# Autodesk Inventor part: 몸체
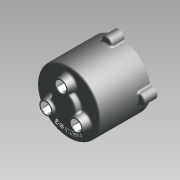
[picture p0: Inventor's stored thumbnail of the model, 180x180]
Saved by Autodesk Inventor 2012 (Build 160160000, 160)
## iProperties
Created: 2012-05
Part Number: 몸체
Document SubType Name: 모델링
Designer: SeoGD™
Material: 알루미늄-6061
Mass: 475.555 g
Surface Area: 687.662 cm^2
Volume: 175.481 cm^3
Density: 2.71 g/cm^3
변환 표준: STEP AP214IS
파일 이름: C:\Users\SeoGD\Desktop\?쒗뿕\紐몄껜.stp
전처리기: Build: 253, Release: 2010 SP1 - Date: Wed 07/29/2009
전송 단위: 밀리미터
불확실성: 0.01
Author: SeoGD™
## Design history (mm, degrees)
sketch "스케치2"
  geometry: C1 r 50 at (0, 0); 1 further point
  constraints: 1 centre point, 1 coincident
  dimensions: "d9" = 100 diameter of C1
extrude "돌출2" new body sketch "스케치2" distance "d10" = 80; taper "d11" = 0 deg
feature "쉘1" dims "d12" = 5
sketch "스케치3" dims "d13" = 55
  geometry: C1 r 7.5 at (0, 27.5); C2 r 12.5 at (0, 27.5); 2 further points
  constraints: 2 centre point, 2 coincident, 2 vertical alignment, 2 other
  dimensions: "d14" = 15 diameter of C1; "d15" = 25 diameter of C2
extrude "돌출3" join sketch "스케치3" distance "d16" = 12; taper "d17" = -10 deg
hole "구멍2" diameter "d20" = 15; stored, may be unused: countersink angle "d24" = 90 deg, drill point angle "d26" = 118 deg; dims "d18" = 10, "d19" = 10, "d21" = 6, "d22" = 4, "d23" = 2, "d25" = 15
chamfer "모따기1" distance "d27" = 1; stored, may be unused: second distance "d28" = 2, angle "d29" = 45 deg
sketch "스케치4"
  geometry: L1 (0, 0)-(0, 88); L2 (0, 70)-(13.16, 70); L3 (-45, 75)-(45, 75) reference; L4 (-50, 80)-(50, 80) reference; L5 (13.16, 70)-(14.5, 75); L6 (20, 80)-(20, 88); L7 (20, 88)-(0, 88); L8 (20, 80)-(14.5, 75)
  constraints: 12 end point, 3 point on line, 2 perpendicular, 1 vertical
  dimensions: "d34" = 40 diameter of L6 L1; "d35" = 105 deg angle of L5 L3; "d36" = 5 distance between parallel lines of L2 L3; "d37" = 8 distance between parallel lines of L7 L4; "d51" = 29 diameter of L5.end L1
revolve "회전1" sketch "스케치4" stored, may be unused: angle "d38" = 90 deg
hole "구멍3" diameter "d41" = 15; stored, may be unused: countersink angle "d45" = 90 deg, drill point angle "d47" = 0 deg; dims "d39" = 10, "d40" = 10, "d42" = 6, "d43" = 22, "d44" = 13, "d46" = 15
chamfer "모따기2" distance "d48" = 1; stored, may be unused: second distance "d49" = 2, angle "d50" = 45 deg
fillet "모깎기1" dims "d52" = 3
fillet "모깎기2" dims "d53" = 3, "d72" = 0.2
sketch "스케치5"
  geometry: A1 r 50 centre (0, 0) between (50, 0) and (-8.074, 49.344) reference; A2 r 8.5 centre (0, 52) between (8.074, 49.344) and (-8.074, 49.344); 1 further point
  constraints: 5 point on circle, 1 centre point, 1 horizontal alignment
  dimensions: "d54" = 90 deg dimension on point (0, 0) A2.centre A1.start; "d55" = 52 distance of A2.centre point (0, 0); "d56" = 17 diameter of A2
extrude "돌출4" join sketch "스케치5" distance "d57" = 20; taper "d58" = 0 deg
fillet "모깎기3" dims "d59" = 3
hole "구멍4" diameter "d62" = 4.134; stored, may be unused: countersink angle "d66" = 90 deg, drill point angle "d68" = 118 deg; dims "d60" = 10, "d61" = 10, "d63" = 12, "d64" = 22, "d65" = 13, "d67" = 15
sketch "스케치6"
  geometry: C1 r 47 at (0, 0) reference; C2 r 42.5 at (0, 0); 1 further point
  constraints: 1 centre point, 1 coincident, 1 other
  dimensions: "d73" = 85 diameter of C2
feature "엠보싱1" sketch "스케치6" dims "d74" = 1, "d75" = 0
node "솔리드1"
node "솔리드 본체"
node "곡면 본체"
pattern_circular "원형 패턴1" dims "d31" = 360 deg
pattern_circular "원형 패턴2" dims "d70" = 360 deg
node "솔리드2"
